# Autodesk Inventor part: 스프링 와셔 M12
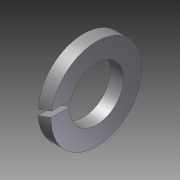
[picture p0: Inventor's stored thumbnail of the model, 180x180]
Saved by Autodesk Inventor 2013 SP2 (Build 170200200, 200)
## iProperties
Created: 2024-07
Part Number: 스프링 와셔 M12
Material: Generic
Document SubType Name: Modeling
Designer: 601
Density: 1 g/cm^3
Author: 601
변환 표준: STEP AP214IS
전처리기: Build: 200, Release: 2013 SP2 Update 6 - Date: Thu 07/17/2014
전송 단위: 밀리미터
불확실성: 0.01
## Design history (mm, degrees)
node "스프링  와셔 M121"
body "Solid1"
node "기준1"
